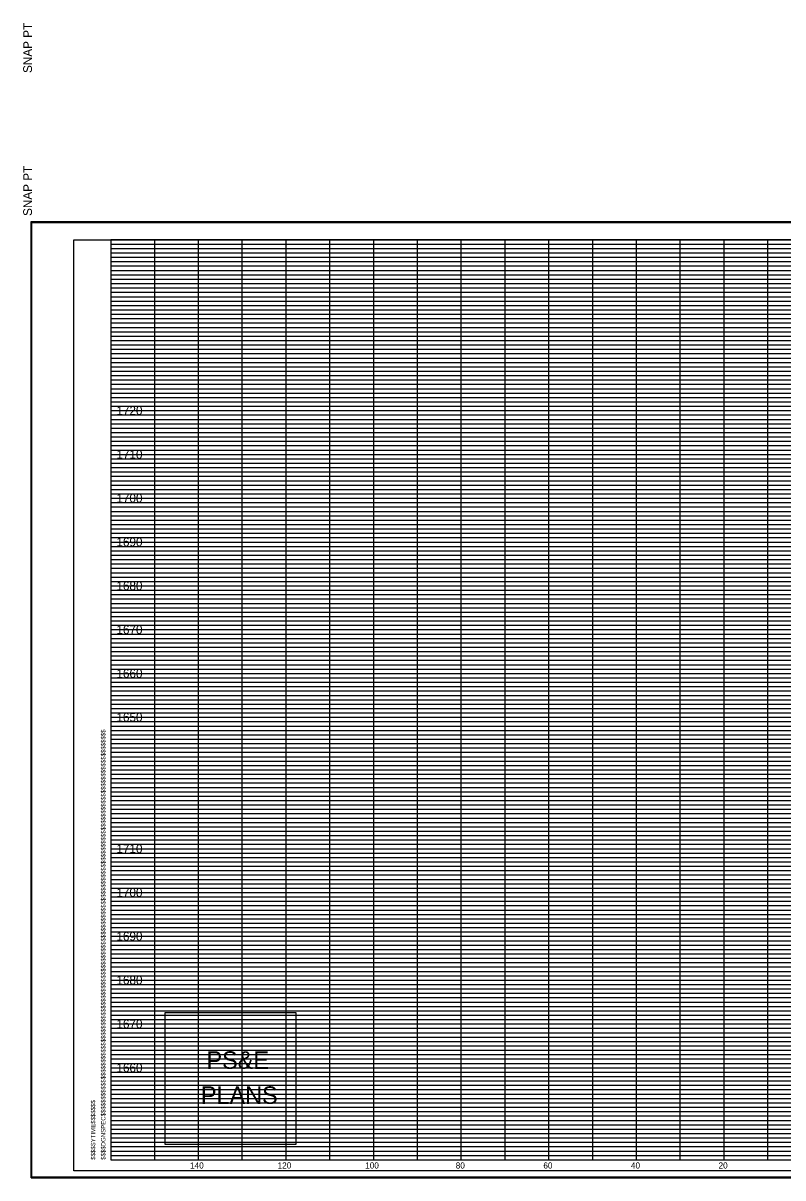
# Model space of a CAD drawing. Extents: x 980 to 2228, y 978 to 2394.
# Drawn here: x 979.9 to 1153.4, y 1265.9 to 1529.4 of the extents above; entities that cross this region are included whole.
import ezdxf

# ---------------------------------------------------------------- set-up
doc = ezdxf.new("R2010")
doc.units = 0
for name, color, linetype in [('DESIGN - SHEET - Corner Text', 7, 'Continuous'), ('DESIGN - SHEET - Light Grid', 7, 'Continuous'), ('DESIGN - SHEET - Linework', 7, 'Continuous'), ('DESIGN - SHEET - Plot Shape', 7, 'Continuous'), ('DESIGN - TYPICAL - Finished Grade and Subgrade', 7, 'Continuous')]:
    doc.layers.add(name, color=color, linetype=linetype)

# ---------------------------------------------------------------- blocks, each defined once
blk = doc.blocks.new('XSTSHT')
at = {"layer": 'DESIGN - SHEET - Light Grid'}
for p, q in [((0, 20.9), (8, 20.9)), ((8, 20.9), (16, 20.9)), ((0, 20.8), (8, 20.8)), ((0, 20.7), (8, 20.7)), ((0, 20.6), (8, 20.6)), ((8, 20.8), (16, 20.8)), ((8, 20.7), (16, 20.7)), ((8, 20.6), (16, 20.6)), ((0, 20.5), (8, 20.5)), ((0, 20.4), (8, 20.4)), ((0, 20.3), (8, 20.3)), ((8, 20.5), (16, 20.5)), ((8, 20.4), (16, 20.4)), ((8, 20.3), (16, 20.3)), ((0, 20.2), (8, 20.2)), ((0, 20.1), (8, 20.1)), ((8, 20.2), (16, 20.2)), ((8, 20.1), (16, 20.1)), ((0, 19.9), (8, 19.9)), ((0, 19.8), (8, 19.8)), ((8, 19.9), (16, 19.9)), ((8, 19.8), (16, 19.8)), ((0, 19.7), (8, 19.7)), ((0, 19.6), (8, 19.6)), ((8, 19.7), (16, 19.7)), ((8, 19.6), (16, 19.6)), ((0, 19.5), (8, 19.5)), ((0, 19.4), (8, 19.4)), ((0, 19.3), (8, 19.3)), ((8, 19.5), (16, 19.5)), ((8, 19.4), (16, 19.4)), ((8, 19.3), (16, 19.3)), ((0, 19.2), (8, 19.2)), ((0, 19.1), (8, 19.1)), ((8, 19.2), (16, 19.2)), ((8, 19.1), (16, 19.1)), ((0, 18.9), (8, 18.9)), ((0, 18.8), (8, 18.8)), ((8, 18.9), (16, 18.9)), ((8, 18.8), (16, 18.8)), ((0, 18.7), (8, 18.7)), ((0, 18.6), (8, 18.6)), ((0, 18.5), (8, 18.5)), ((8, 18.7), (16, 18.7)), ((8, 18.6), (16, 18.6)), ((8, 18.5), (16, 18.5)), ((0, 18.4), (8, 18.4)), ((0, 18.3), (8, 18.3)), ((0, 18.2), (8, 18.2)), ((8, 18.4), (16, 18.4)), ((8, 18.3), (16, 18.3)), ((8, 18.2), (16, 18.2)), ((0, 18.1), (8, 18.1)), ((8, 18.1), (16, 18.1)), ((0, 17.9), (8, 17.9)), ((0, 17.8), (8, 17.8)), ((0, 17.7), (8, 17.7)), ((8, 17.9), (16, 17.9)), ((8, 17.8), (16, 17.8)), ((8, 17.7), (16, 17.7)), ((0, 17.6), (8, 17.6)), ((0, 17.5), (8, 17.5)), ((0, 17.4), (8, 17.4)), ((8, 17.6), (16, 17.6)), ((8, 17.5), (16, 17.5)), ((8, 17.4), (16, 17.4)), ((0, 17.3), (8, 17.3)), ((0, 17.2), (8, 17.2)), ((8, 17.3), (16, 17.3)), ((8, 17.2), (16, 17.2)), ((0, 17.1), (8, 17.1)), ((0, 16.9), (8, 16.9)), ((8, 17.1), (16, 17.1)), ((8, 16.9), (16, 16.9)), ((0, 16.8), (8, 16.8)), ((0, 16.7), (8, 16.7)), ((8, 16.8), (16, 16.8)), ((8, 16.7), (16, 16.7)), ((0, 16.6), (8, 16.6)), ((0, 16.5), (8, 16.5)), ((0, 16.4), (8, 16.4)), ((8, 16.6), (16, 16.6)), ((8, 16.5), (16, 16.5)), ((8, 16.4), (16, 16.4)), ((0, 16.3), (8, 16.3)), ((0, 16.2), (8, 16.2)), ((0, 16.1), (8, 16.1)), ((8, 16.3), (16, 16.3)), ((8, 16.2), (16, 16.2)), ((8, 16.1), (16, 16.1)), ((0, 15.9), (8, 15.9)), ((8, 15.9), (16, 15.9)), ((0, 15.8), (8, 15.8)), ((0, 15.7), (8, 15.7)), ((0, 15.6), (8, 15.6)), ((8, 15.8), (16, 15.8)), ((8, 15.7), (16, 15.7)), ((8, 15.6), (16, 15.6)), ((0, 15.5), (8, 15.5)), ((0, 15.4), (8, 15.4)), ((0, 15.3), (8, 15.3)), ((8, 15.5), (16, 15.5)), ((8, 15.4), (16, 15.4)), ((8, 15.3), (16, 15.3)), ((0, 15.2), (8, 15.2)), ((0, 15.1), (8, 15.1)), ((8, 15.2), (16, 15.2)), ((8, 15.1), (16, 15.1)), ((0, 14.9), (8, 14.9)), ((0, 14.8), (8, 14.8)), ((8, 14.9), (16, 14.9)), ((8, 14.8), (16, 14.8)), ((0, 14.7), (8, 14.7)), ((0, 14.6), (8, 14.6)), ((0, 14.5), (8, 14.5)), ((8, 14.7), (16, 14.7)), ((8, 14.6), (16, 14.6)), ((8, 14.5), (16, 14.5)), ((0, 14.4), (8, 14.4)), ((0, 14.3), (8, 14.3)), ((8, 14.4), (16, 14.4)), ((8, 14.3), (16, 14.3)), ((0, 14.2), (8, 14.2)), ((0, 14.1), (8, 14.1)), ((8, 14.2), (16, 14.2)), ((8, 14.1), (16, 14.1)), ((0, 13.9), (8, 13.9)), ((0, 13.8), (8, 13.8)), ((8, 13.9), (16, 13.9)), ((8, 13.8), (16, 13.8)), ((0, 13.7), (8, 13.7)), ((0, 13.6), (8, 13.6)), ((0, 13.5), (8, 13.5)), ((8, 13.7), (16, 13.7)), ((8, 13.6), (16, 13.6)), ((8, 13.5), (16, 13.5)), ((0, 13.4), (8, 13.4)), ((0, 13.3), (8, 13.3)), ((0, 13.2), (8, 13.2)), ((8, 13.4), (16, 13.4)), ((8, 13.3), (16, 13.3)), ((8, 13.2), (16, 13.2)), ((0, 13.1), (8, 13.1)), ((8, 13.1), (16, 13.1)), ((0, 12.9), (8, 12.9)), ((0, 12.8), (8, 12.8)), ((0, 12.7), (8, 12.7)), ((8, 12.9), (16, 12.9)), ((8, 12.8), (16, 12.8)), ((8, 12.7), (16, 12.7)), ((0, 12.6), (8, 12.6)), ((0, 12.5), (8, 12.5)), ((0, 12.4), (8, 12.4)), ((8, 12.6), (16, 12.6)), ((8, 12.5), (16, 12.5)), ((8, 12.4), (16, 12.4)), ((0, 12.3), (8, 12.3)), ((0, 12.2), (8, 12.2)), ((8, 12.3), (16, 12.3)), ((8, 12.2), (16, 12.2)), ((0, 12.1), (8, 12.1)), ((0, 11.9), (8, 11.9)), ((8, 12.1), (16, 12.1)), ((8, 11.9), (16, 11.9)), ((0, 11.8), (8, 11.8)), ((0, 11.7), (8, 11.7)), ((0, 11.6), (8, 11.6)), ((8, 11.8), (16, 11.8)), ((8, 11.7), (16, 11.7)), ((8, 11.6), (16, 11.6)), ((0, 11.5), (8, 11.5)), ((0, 11.4), (8, 11.4)), ((8, 11.5), (16, 11.5)), ((8, 11.4), (16, 11.4)), ((0, 11.3), (8, 11.3)), ((0, 11.2), (8, 11.2)), ((0, 11.1), (8, 11.1)), ((8, 11.3), (16, 11.3)), ((8, 11.2), (16, 11.2)), ((8, 11.1), (16, 11.1)), ((0, 10.9), (8, 10.9)), ((8, 10.9), (16, 10.9)), ((0, 10.8), (8, 10.8)), ((0, 10.7), (8, 10.7)), ((0, 10.6), (8, 10.6)), ((8, 10.8), (16, 10.8)), ((8, 10.7), (16, 10.7)), ((8, 10.6), (16, 10.6)), ((0, 10.5), (8, 10.5)), ((0, 10.4), (8, 10.4)), ((0, 10.3), (8, 10.3)), ((8, 10.5), (16, 10.5)), ((8, 10.4), (16, 10.4)), ((8, 10.3), (16, 10.3)), ((0, 10.2), (8, 10.2)), ((0, 10.1), (8, 10.1)), ((8, 10.2), (16, 10.2)), ((8, 10.1), (16, 10.1)), ((0, 9.9), (8, 9.9)), ((0, 9.8), (8, 9.8)), ((8, 9.9), (16, 9.9)), ((8, 9.8), (16, 9.8)), ((0, 9.7), (8, 9.7)), ((0, 9.6), (8, 9.6)), ((0, 9.5), (8, 9.5)), ((8, 9.7), (16, 9.7)), ((8, 9.6), (16, 9.6)), ((8, 9.5), (16, 9.5)), ((0, 9.4), (8, 9.4)), ((0, 9.3), (8, 9.3)), ((8, 9.4), (16, 9.4)), ((8, 9.3), (16, 9.3)), ((0, 9.2), (8, 9.2)), ((0, 9.1), (8, 9.1)), ((8, 9.2), (16, 9.2)), ((8, 9.1), (16, 9.1)), ((0, 8.9), (8, 8.9)), ((0, 8.8), (8, 8.8)), ((0, 8.7), (8, 8.7)), ((8, 8.9), (16, 8.9)), ((8, 8.8), (16, 8.8)), ((8, 8.7), (16, 8.7)), ((0, 8.6), (8, 8.6)), ((0, 8.5), (8, 8.5)), ((8, 8.6), (16, 8.6)), ((8, 8.5), (16, 8.5)), ((0, 8.4), (8, 8.4)), ((0, 8.3), (8, 8.3)), ((0, 8.2), (8, 8.2)), ((8, 8.4), (16, 8.4)), ((8, 8.3), (16, 8.3)), ((8, 8.2), (16, 8.2)), ((0, 8.1), (8, 8.1)), ((8, 8.1), (16, 8.1)), ((0, 7.9), (8, 7.9)), ((0, 7.8), (8, 7.8)), ((0, 7.7), (8, 7.7)), ((8, 7.9), (16, 7.9)), ((8, 7.8), (16, 7.8)), ((8, 7.7), (16, 7.7)), ((0, 7.6), (8, 7.6)), ((0, 7.5), (8, 7.5)), ((0, 7.4), (8, 7.4)), ((8, 7.6), (16, 7.6)), ((8, 7.5), (16, 7.5)), ((8, 7.4), (16, 7.4)), ((0, 7.3), (8, 7.3)), ((0, 7.2), (8, 7.2)), ((8, 7.3), (16, 7.3)), ((8, 7.2), (16, 7.2)), ((0, 7.1), (8, 7.1)), ((0, 6.9), (8, 6.9)), ((8, 7.1), (16, 7.1)), ((8, 6.9), (16, 6.9)), ((0, 6.8), (8, 6.8)), ((0, 6.7), (8, 6.7)), ((0, 6.6), (8, 6.6)), ((8, 6.8), (16, 6.8)), ((8, 6.7), (16, 6.7)), ((8, 6.6), (16, 6.6)), ((0, 6.5), (8, 6.5)), ((0, 6.4), (8, 6.4)), ((8, 6.5), (16, 6.5)), ((8, 6.4), (16, 6.4)), ((0, 6.3), (8, 6.3)), ((0, 6.2), (8, 6.2)), ((0, 6.1), (8, 6.1)), ((8, 6.3), (16, 6.3)), ((8, 6.2), (16, 6.2)), ((8, 6.1), (16, 6.1)), ((0, 5.9), (8, 5.9)), ((0, 5.8), (8, 5.8)), ((8, 5.9), (16, 5.9)), ((8, 5.8), (16, 5.8)), ((0, 5.7), (8, 5.7)), ((0, 5.6), (8, 5.6)), ((8, 5.7), (16, 5.7)), ((8, 5.6), (16, 5.6)), ((0, 5.5), (8, 5.5)), ((0, 5.4), (8, 5.4)), ((0, 5.3), (8, 5.3)), ((8, 5.5), (16, 5.5)), ((8, 5.4), (16, 5.4)), ((8, 5.3), (16, 5.3)), ((0, 5.2), (8, 5.2)), ((0, 5.1), (8, 5.1)), ((8, 5.2), (16, 5.2)), ((8, 5.1), (16, 5.1)), ((0, 4.9), (8, 4.9)), ((0, 4.8), (8, 4.8)), ((8, 4.9), (16, 4.9)), ((8, 4.8), (16, 4.8)), ((0, 4.7), (8, 4.7)), ((0, 4.6), (8, 4.6)), ((0, 4.5), (8, 4.5)), ((8, 4.7), (16, 4.7)), ((8, 4.6), (16, 4.6)), ((8, 4.5), (16, 4.5)), ((0, 4.4), (8, 4.4)), ((0, 4.3), (8, 4.3)), ((8, 4.4), (16, 4.4)), ((8, 4.3), (16, 4.3)), ((0, 4.2), (8, 4.2)), ((0, 4.1), (8, 4.1)), ((8, 4.2), (16, 4.2)), ((8, 4.1), (16, 4.1)), ((0, 3.9), (8, 3.9)), ((0, 3.8), (8, 3.8)), ((0, 3.7), (8, 3.7)), ((8, 3.9), (16, 3.9)), ((8, 3.8), (16, 3.8)), ((8, 3.7), (16, 3.7)), ((0, 3.6), (8, 3.6)), ((0, 3.5), (8, 3.5)), ((8, 3.6), (16, 3.6)), ((8, 3.5), (16, 3.5)), ((0, 3.4), (8, 3.4)), ((0, 3.3), (8, 3.3)), ((0, 3.2), (8, 3.2)), ((8, 3.4), (16, 3.4)), ((8, 3.3), (16, 3.3)), ((8, 3.2), (16, 3.2)), ((0, 3.1), (8, 3.1)), ((0, 2.9), (8, 2.9)), ((8, 3.1), (16, 3.1)), ((8, 2.9), (16, 2.9)), ((0, 2.8), (8, 2.8)), ((0, 2.7), (8, 2.7)), ((8, 2.8), (16, 2.8)), ((8, 2.7), (16, 2.7)), ((0, 2.6), (8, 2.6)), ((0, 2.5), (8, 2.5)), ((0, 2.4), (8, 2.4)), ((8, 2.6), (16, 2.6)), ((8, 2.5), (16, 2.5)), ((8, 2.4), (16, 2.4)), ((0, 2.3), (8, 2.3)), ((0, 2.2), (8, 2.2)), ((8, 2.3), (16, 2.3)), ((8, 2.2), (16, 2.2)), ((0, 2.1), (8, 2.1)), ((0, 1.9), (8, 1.9)), ((8, 2.1), (16, 2.1)), ((8, 1.9), (16, 1.9)), ((0, 1.8), (8, 1.8)), ((0, 1.7), (8, 1.7)), ((0, 1.6), (8, 1.6)), ((8, 1.8), (16, 1.8)), ((8, 1.7), (16, 1.7)), ((8, 1.6), (16, 1.6)), ((0, 1.5), (8, 1.5)), ((0, 1.4), (8, 1.4)), ((8, 1.5), (16, 1.5)), ((8, 1.4), (16, 1.4)), ((0, 1.3), (8, 1.3)), ((0, 1.2), (8, 1.2)), ((0, 1.1), (8, 1.1)), ((8, 1.3), (16, 1.3)), ((8, 1.2), (16, 1.2)), ((8, 1.1), (16, 1.1)), ((0, 0.9), (8, 0.9)), ((0, 0.8), (8, 0.8)), ((8, 0.9), (16, 0.9)), ((8, 0.8), (16, 0.8)), ((0, 0.7), (8, 0.7)), ((0, 0.6), (8, 0.6)), ((8, 0.7), (16, 0.7)), ((8, 0.6), (16, 0.6)), ((0, 0.5), (8, 0.5)), ((0, 0.4), (8, 0.4)), ((0, 0.3), (8, 0.3)), ((8, 0.5), (16, 0.5)), ((8, 0.4), (16, 0.4)), ((8, 0.3), (16, 0.3)), ((0, 0.2), (8, 0.2)), ((0, 0.1), (8, 0.1)), ((8, 0.2), (16, 0.2)), ((8, 0.1), (16, 0.1))]:
    blk.add_line(p, q, dxfattribs=at)
at = {"layer": 'DESIGN - SHEET - Linework'}
for p, q in [((-1.823, -0.414), (-1.823, 21.414)), ((-1.823, 21.414), (32.217, 21.414)), ((1, 0), (1, 21)), ((2, 0), (2, 21)), ((3, 0), (3, 21)), ((4, 0), (4, 21)), ((5, 0), (5, 21)), ((6, 0), (6, 21)), ((7, 0), (7, 21)), ((8, 0), (8, 21)), ((9, 0), (9, 21)), ((10, 0), (10, 21)), ((11, 0), (11, 21)), ((12, 0), (12, 21)), ((13, 0), (13, 21)), ((14, 0), (14, 21)), ((15, 0), (15, 21)), ((0, 20), (28, 20)), ((0, 19), (32, 19)), ((0, 18), (32, 18)), ((0, 17), (32, 17)), ((0, 16), (32, 16)), ((0, 15), (32, 15)), ((0, 14), (32, 14)), ((0, 13), (32, 13)), ((0, 12), (32, 12)), ((0, 11), (32, 11)), ((0, 10), (32, 10)), ((0, 9), (32, 9)), ((0, 8), (32, 8)), ((0, 7), (32, 7)), ((0, 6), (32, 6)), ((0, 5), (32, 5)), ((0, 4), (32, 4)), ((0, 3), (32, 3)), ((0, 2), (32, 2)), ((0, 1), (32, 1)), ((-1.823, -0.414), (32.217, -0.414))]:
    blk.add_line(p, q, dxfattribs=at)
blk.add_lwpolyline([(0, 21), (0, 0), (32, 0), (32, 21), (0, 21)], dxfattribs=at)
at = {"layer": 'DESIGN - SHEET - Plot Shape'}
for points in [[(-1.803, 21.394), (32.197, 21.394), (32.197, -0.394), (-1.803, -0.394)], [(-0.85, 21), (32, 21), (32, -0.25), (-0.85, -0.25)]]:
    blk.add_lwpolyline(points, close=True, dxfattribs=at)
at = {"layer": 'DESIGN - SHEET - Corner Text'}
for s, height, p in [('  SNAP PT', 0.2, (-1.803, 21.394)), ('$$$$DGNSPEC$$$$$$$$$$$$$$$$$$$$$$$$$$$$$$$$$$$$$$$$$$$$$$$$$$$$$$$$$$$$$$$$$$$$$$$$$$$$$$$$$$$$$$$$$$$$$$$$$$$$$$$$$$$$$$$$$$$', 0.100002, (-0.126, 0)), ('$$$$SYTIME$$$$$$$', 0.1, (-0.358, 0)), ('SNAP PT  ', 0.2, (-1.803, -2.194))]:
    blk.add_text(s, height=height, rotation=90, dxfattribs=at).set_placement(p)

msp = doc.modelspace()

# ---------------------------------------------------------------- linework, layer by layer
at = {"layer": 'DESIGN - SHEET - Corner Text'}
msp.add_lwpolyline([(1012.3, 1303.57), (1012.3, 1273.57), (1042.3, 1273.57), (1042.3, 1303.57)], close=True, dxfattribs=at)
at = {"layer": 'DESIGN - SHEET - Plot Shape'}
msp.add_lwpolyline([(991.5, 1480), (1320, 1480), (1320, 1267.5), (991.5, 1267.5)], close=True, dxfattribs=at)

# ---------------------------------------------------------------- block references
at = {"layer": 'DESIGN - TYPICAL - Finished Grade and Subgrade', "xscale": 10, "yscale": 10}
for p in [(1000, 1540), (1000, 1270)]:
    msp.add_blockref('XSTSHT', p, dxfattribs=at)

# ---------------------------------------------------------------- texts
at = {"layer": 'DESIGN - SHEET - Corner Text'}
for s, height, p in [('1720', 2, (1001.25, 1440)), ('1710', 2, (1001.25, 1430)), ('1700', 2, (1001.25, 1420)), ('1690', 2, (1001.25, 1410)), ('1680', 2, (1001.25, 1400)), ('1670', 2, (1001.25, 1390)), ('1660', 2, (1001.25, 1380)), ('1650', 2, (1001.25, 1370)), ('1710', 2, (1001.25, 1340)), ('1700', 2, (1001.25, 1330)), ('1690', 2, (1001.25, 1320)), ('1680', 2, (1001.25, 1310)), ('1670', 2, (1001.25, 1300)), ('PS&E', 4, (1021.82, 1290.75)), ('1660', 2, (1001.25, 1290)), ('PLANS', 4, (1020.54, 1282.75)), ('140', 1.4, (1018.06, 1268)), ('120', 1.4, (1038.06, 1268)), ('100', 1.4, (1058.06, 1268)), ('80', 1.4, (1078.74, 1268)), ('60', 1.4, (1098.74, 1268)), ('40', 1.4, (1118.74, 1268)), ('20', 1.4, (1138.74, 1268))]:
    msp.add_text(s, height=height, dxfattribs=at).set_placement(p)

doc.saveas('drawing.dxf')
